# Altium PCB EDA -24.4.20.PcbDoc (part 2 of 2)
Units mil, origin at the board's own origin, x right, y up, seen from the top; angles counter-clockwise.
Board outline 1259.84 x 1062.87 mil, 4 copper layers (Top1, Gnd2, Signal3, Bottom4), stack 30.634 mil thick; 95 components, 111 nets, 499 pads, 259 vias.
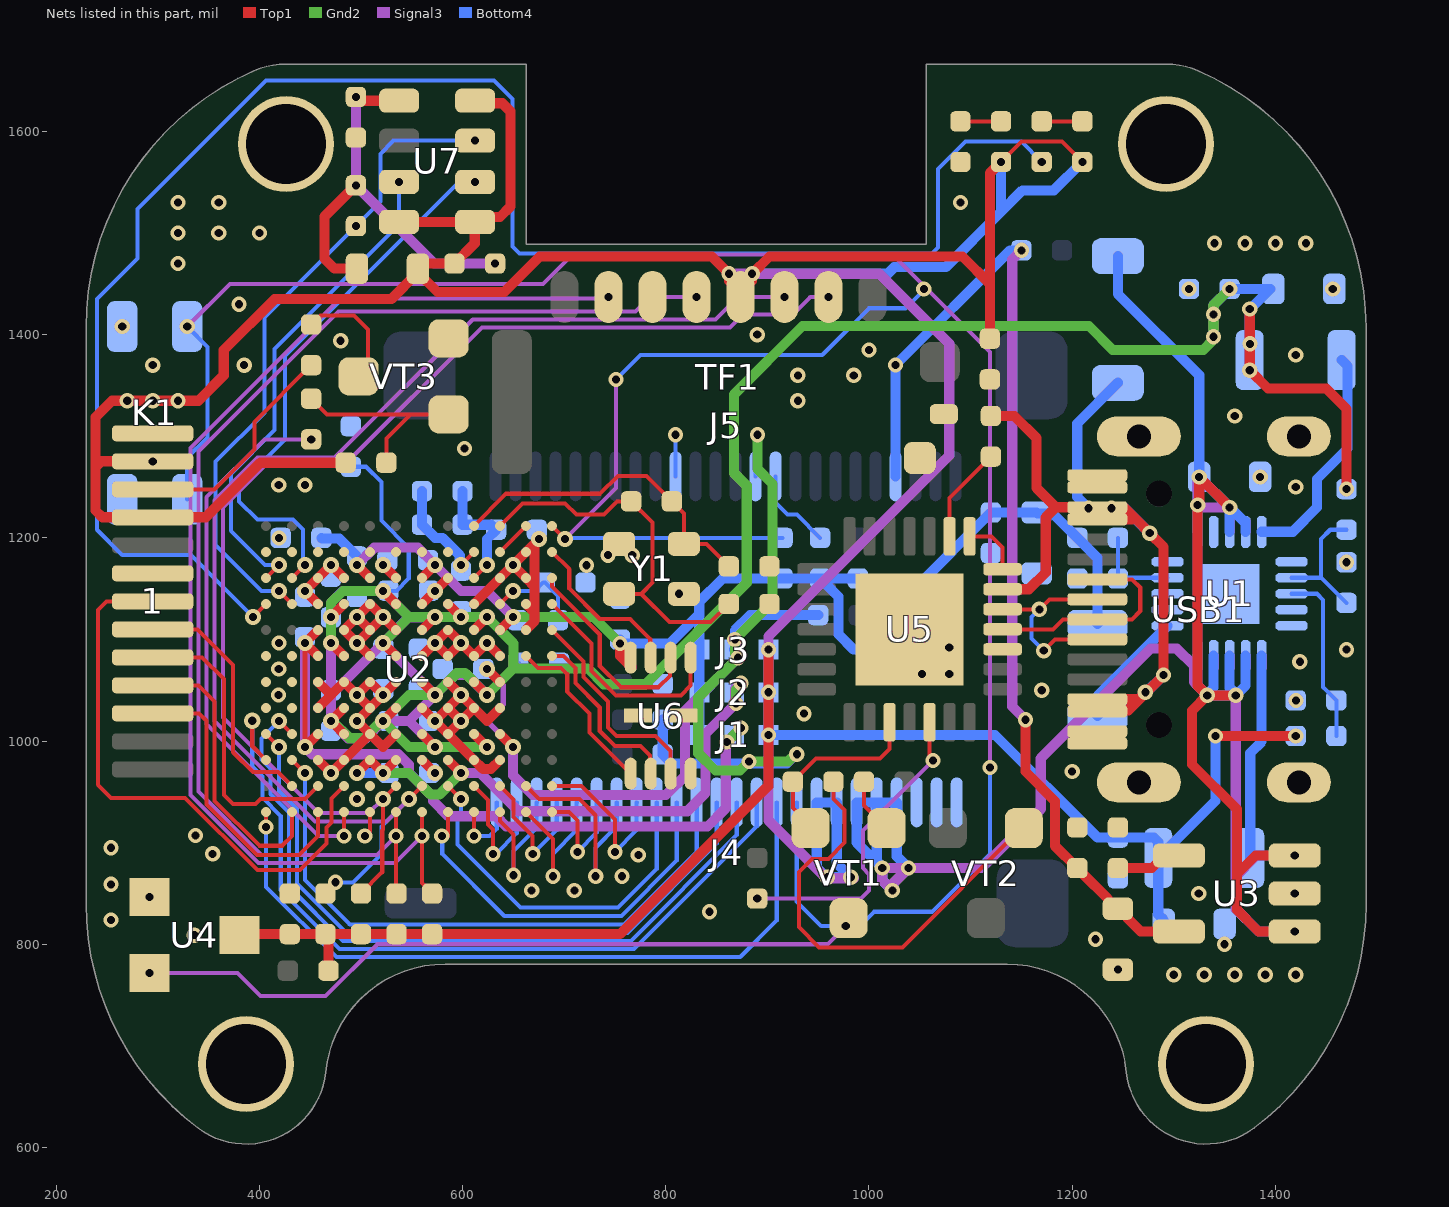
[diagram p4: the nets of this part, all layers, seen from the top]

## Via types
v1: diameter 15, hole 8, Top1 to Bottom4, tented both sides, 192 vias
v2: diameter 16, hole 8, Top1 to Bottom4, tented both sides, 67 vias

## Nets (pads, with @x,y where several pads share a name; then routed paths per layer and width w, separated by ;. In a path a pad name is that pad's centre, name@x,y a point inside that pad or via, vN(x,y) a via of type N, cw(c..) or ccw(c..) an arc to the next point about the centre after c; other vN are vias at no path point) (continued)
GND: 1.8 1.13 C1.1 C2.2 C3.1 C4.1 C5.1 C6.1 C7.1 C8.1 C9.1 C10.1 C11.1 C12.1 C13.1 C14.1 C15.1 C16.2 C17.1 C18.1 C19.2 C20.1 C21.2 C22.2 C23.1 C24.2 C25.2 C26.2 C27.2 C30.2 C33.2 C35.2 C36.2 D1.2 J4.22 J4.23 J4.24 J5.15 K1.1 K1.3 pad. R2.1 R4.1 R9.1 R15.1 R23.2 R30.2 TF1.6 TF1.9 TF1.10 U1.1 U1.4 U1.5 U1.12 U1.13 U1.15 U1.17 U1.21 U2.C3 U2.C4 U2.C6 U2.C9 U2.C10 U2.D5 U2.D7 U2.D8 U2.E3 U2.E4 U2.E5 U2.E6 U2.E8 U2.E10 U2.F5 U2.F7 U2.F8 U2.F9 U2.F10 U2.G3 U2.G4 U2.G5 U2.G6 U2.G8 U2.H2 U2.H5 U2.H7 U2.H8 U2.H9 U2.J2 U2.J4 U2.J6 U2.J8 U2.J10 U2.K2 U2.K3 U2.K5 U2.K7 U2.K9 U2.K10 U2.L2 U3.2 U4.1 U5.3 U5.29 U6.4 U6.GNDA U6.GNDB USB1.1 USB1.2 USB1.3 USB1.4 USB1.A1 USB1.A12 USB1.B1 USB1.B12 VT3.2 Y1.2 Y1.4 | length 1297
  Top1 w9.84: U2.C10@457.64,981.46 v2(470.43,968.66) U2.C9@483.23,981.46 496.02,994.25 U2.D8@508.82,1007.05 ; U2.E10@457.64,1032.64 470.43,1045.43 ; U2.F10@457.64,1058.23 470.43,1045.43 ; U2.J10@457.64,1135 v2(444.84,1147.8) U2.K10@457.64,1160.59 v2(470.43,1173.39) U2.K9@483.23,1160.59 ; U2.G8@508.82,1083.82 v2(496.02,1096.61) ; v2(521.61,1173.39) U2.K7@534.41,1160.59 ; U2.D7@534.41,1007.05 521.61,994.25 U2.D8@508.82,1007.05 ; U2.F7@534.41,1058.23 v2(521.61,1045.43) ; U2.H7@534.41,1109.41 v2(521.61,1122.21) ; U2.C6@560,981.46 v2(572.8,968.66) ; U2.E6@560,1032.64 v2(572.8,1019.84) ; U2.G6@560,1083.82 v2(572.8,1096.61) ; U2.J6@560,1135 v2(572.8,1147.8) U2.K5@585.59,1160.59 ; U2.F5@585.59,1058.23 v2(598.39,1045.43) ; U2.J4@611.18,1135 U2.K3@636.77,1160.59 v2(649.57,1173.39) ; U2.C3@636.77,981.46 628.05,972.74 619.9,972.74 U2.C4@611.18,981.46 U2.D5@585.59,1007.05 ; U2.E3@636.77,1032.64 623.98,1019.84 U2.E4@611.18,1032.64 ; U2.G3@636.77,1083.82 623.98,1096.61 U2.G4@611.18,1083.82 v2(598.39,1096.61) ; U2.H2@662.36,1109.41 662.36,1109.57 671,1118.21 671,1126.36 ; U2.J2@662.36,1134.84 U2.J2@662.36,1135 671,1126.36 ; 470.43,1045.43 U2.F9@483.23,1058.23 v2(496.02,1045.43) ; v2(496.02,1045.43) U2.E8@508.82,1032.64 ; v2(496.02,1045.43) U2.F8@508.82,1058.23 v2(521.61,1045.43) ; v2(496.02,1096.61) U2.H9@483.23,1109.41 v2(496.02,1122.21) ; v2(496.02,1096.61) U2.H8@508.82,1109.41 ; v2(496.02,1122.21) U2.J8@508.82,1135 v2(521.61,1122.21) ; v2(496.02,1122.21) U2.H8@508.82,1109.41 ; U2.D8@508.82,1007.05 v2(496.02,1019.84) U2.E8@508.82,1032.64 ; U2.E8@508.82,1032.64 v2(521.61,1045.43) ; U2.H8@508.82,1109.41 v2(521.61,1122.21) ; v2(572.8,1019.84) U2.E5@585.59,1032.64 ; v2(572.8,1019.84) U2.D5@585.59,1007.05 ; v2(572.8,1096.61) U2.H5@585.59,1109.41 v2(598.39,1096.61) ; v2(572.8,1096.61) U2.G5@585.59,1083.82 v2(598.39,1096.61) ; U2.D5@585.59,1007.05 v2(598.39,1019.84) ; U2.E5@585.59,1032.64 v2(598.39,1045.43) ; U2.E5@585.59,1032.64 v2(598.39,1019.84) ; v2(598.39,1019.84) U2.E4@611.18,1032.64 ; v2(598.39,1045.43) U2.E4@611.18,1032.64 ; v2(649.57,1173.39) U2.L2@662.36,1186.18 v2(675.16,1198.98) 675.16,1197.31 671,1193.15 671,1151.95 ; v2(649.57,1173.39) U2.K2@662.36,1160.59 671,1151.95 ; 671,1126.36 671,1151.95
  Bottom4 w4: J5.15@809.62,1260.59 v1(809.62,1301.51)
  other v1: 1300,770 1330,770 1360,770 1390,770 1420,770 1245,775 1350,800 1223,805 336,809 254,824 843,832 291.71,846.4 1324.57,850 1419.06,850 668,853 710,853 254,859 757,867 773,888 354,889 254,895 337,907 1200,970 936,1027 1420.31,1040 418.75,1045.39 1170,1050 1052,1066 1079,1066 419,1071 1424.06,1078.07 1470,1090 1079,1092 419.25,1096.61 813,1145 722,1173 1470,1176 743,1183 767,1183 419.25,1200 1420,1250 419,1252 445,1252 1385,1260 602,1288 1360,1320 930,1335 930,1360 985,1360 295,1370 385,1370 1420,1380 1000,1385 480,1394 890,1400 265,1408 380,1430 1315,1445 1456.5,1445 320,1470 1340,1490 1370,1490 1400,1490 1430,1490 320,1500 360,1500 400,1500 320,1530 360,1530 1090,1530
  other v2: 496.02,943.07 623.98,1096.61
IO_6: U2.G11
IO_7: U2.G12
IO_8: U2.F11
IO_9: U2.F12
IO_10: U2.E11
IO_11: U2.E12
IO_12: J4.13 U2.D11 | length 737.9
  Top1 w4: v2(419.25,1019.84) U2.D11@432.05,1007.05
  Bottom4 w4: v2(419.25,1019.84) 402,1002.59 402,982 411,973 411,947.69 429,929.69 429,856.63 482.33,803.29 765.55,803.29 869.83,907.57 J4.13@869.83,939.71
IO_13: J4.12 U2.D12 | length 670
  Top1 w4: U2.D12@406.46,1007.05 v2(419.25,994.25)
  Bottom4 w4: v2(419.25,994.25) 419.25,950.75 437,933 437,859.94 485.65,811.29 762.23,811.29 850.14,899.2 J4.12@850.14,939.71
IO_14: J4.11 U2.C11 | length 605.7
  Top1 w4: U2.C11@432.05,981.46 v2(444.84,968.66)
  Bottom4 w4: v2(444.84,968.66) 445,968.5 445,863.25 488.96,819.29 758.92,819.29 830.46,890.83 J4.11@830.46,939.71
IO_15: J4.14 U2.C12 | length 788.7
  Top1 w4: v2(393,1020) 393,994.91 U2.C12@406.46,981.46
  Bottom4 w4: v2(393,1020) 393,975 403,965 403,944.37 421,926.37 421,853.31 479.02,795.29 768.86,795.29 889.51,915.94 J4.14@889.51,939.71
IO_17: J4.15 U2.A12 | length 736.5
  Top1 w4: v1(406.46,915.46) U2.A12@406.46,930.28
  Bottom4 w4: v1(406.46,915.46) 406.46,856.54 475.71,787.29 873.29,787.29 909.2,823.2 J4.15@909.2,939.71
IO_18: 1.6 U2.B11 | length 251.3
  Top1 w4: 1.6@295,1110 339,1110 374,1075 374,989 393.63,969.37 418.55,969.37 U2.B11@432.05,955.87
IO_19: 1.4 U2.A11 | length 287.5
  Top1 w4: 1.4@295,1054.88 340.13,1054.88 356,1039.02 356,941 400,897 422.5,897 432.05,906.54 U2.A11@432.05,930.28
IO_20: 1.5 U2.B10 | length 296.6
  Top1 w4: 1.5@295,1082.44 343.56,1082.44 365,1061 365,947 374,938 396,938 401,943 444.77,943 U2.B10@457.64,955.87
IO_21: 1.3 U2.A10 | length 300
  Top1 w4: 1.3@295,1027.32 340.68,1027.32 348,1020 348,937.69 397.69,888 439.09,888 457.64,906.54 U2.A10@457.64,930.28
IO_22: 1.7 U2.B9 | length 564.1
  Top1 w4: 1.7@295,1137.56 249.56,1137.56 241,1129 241,957 254,944 327,944 398,873 440,873 466,899 466,915 471,920 471,943.64 U2.B9@483.23,955.87
IO_23: R20.2 U2.A9 | length 555.5
  Top1 w4: v1(483.23,906.54) U2.A9@483.23,930.28
  Signal3 w4: v1@452,1297 v1(451,1297) 405,1297 348,1240 348,1016.62 458.08,906.54 v1(483.23,906.54)
IO_24: U2.B8
IO_25: U2.A8 | length 25.8
  Top1 w4: v1(503.82,906.54) 508.82,911.54 U2.A8@508.82,930.28
IO_26: R24.1 TF1.2 U2.B7 | length 1211.4
  Top1 w4: R24.1@500,850 520.91,870.91 520.91,912.14 521.61,912.84 v2(521.61,943.07) U2.B7@534.41,955.87
  Signal3 w4: v2(521.61,943.07) 507.54,929 458.25,929 364,1023.25 364,1230 405,1271 483,1271 619,1407 863.21,1407 876.21,1420 925,1420 942.21,1437.21 v1(960.2,1437.21)
IO_27: R26.1 TF1.5 U2.A7 | length 1196.4
  Top1 w4: U2.A7@534.41,930.28 v1(534.41,906.54) 534.41,850.59 R26.1@535,850
  Signal3 w4: v1(534.41,906.54) 515.87,888 402.31,888 340,950.31 340,1285 478,1423 770,1423 784.21,1437.21 v1(830.28,1437.21)
IO_28: R25.1 TF1.3 U2.B6 | length 1256.9
  Top1 w4: R25.1@465,850 v1@475.5,860.5 ; v2(547.2,943.07) U2.B6@560,955.87
  Signal3 w4: v2(547.2,943.07) 525.13,921 454.94,921 356,1019.94 356,1236.69 398.31,1279 474,1279 610,1415 849,1415 871.21,1437.21 v1(916.9,1437.21)
  Bottom4 w4: v1(475,861) 492,861 520,889 520,915.87 v2(547.2,943.07)
IO_29: R27.1 TF1.7 U2.A6 | length 1165.8
  Top1 w4: U2.A6@560,930.28 v1(560,906.54) 560,860.34 570,850.34 R27.1@570,850
  Signal3 w4: v1(560,906.54) 533.46,880 399,880 332,947 332,1288.31 479.19,1435.5 741.96,1435.5 v1(743.67,1437.21)
IO_30: J4.9 U2.B5 | length 367.7
  Top1 w4: U2.B5@585.59,955.87 v2(598.39,943.07)
  Bottom4 w4: v2(598.39,943.07) 598.39,928.39 595,925 595,898 657,836 753,836 791.09,874.09 J4.9@791.09,939.71
IO_31: J4.10 U2.A5 | length 377.3
  Top1 w4: v1@585.59,906.54 U2.A5@585.59,930.28
  Bottom4 w4: v1(579.59,906.54) 580,906.13 580,889 641,828 756.31,828 810.77,882.46 J4.10@810.77,939.71
IO_32: J4.2 U2.B4 | length 136.8
  Top1 w4: U2.B4@611.18,955.87 625,942.05 625,918 630,913 v1(630,889)
  Bottom4 w4: v1(630,889) 633,889 653.29,909.29 J4.2@653.29,939.71
IO_33: J4.1 U2.A4 | length 75.2
  Top1 w4: v1(611.18,906.54) U2.A4@611.18,930.28
  Bottom4 w4: v1(611.18,906.54) 626.54,906.54 633.61,913.61 J4.1@633.61,939.71
IO_34: J4.4 U2.B3 | length 140.7
  Top1 w4: U2.B3@636.77,955.87 650,942.64 650,925.36 669,906.36 v1(669,889)
  Bottom4 w4: v1(669,889) 692.66,912.66 J4.4@692.66,939.71
IO_35: J4.3 U2.A3 | length 149
  Top1 w4: U2.A3@636.77,930.28 636.77,921.23 650,908 v1(650,868)
  Bottom4 w4: v1(650,868) 650,892 672.57,914.57 672.57,939.3 J4.3@672.98,939.71
IO_36: J4.5 U2.A2 | length 156.7
  Top1 w4: U2.A2@662.36,930.28 689,903.64 v1(689,867)
  Bottom4 w4: v1(689,867) 689,889 712.26,912.26 712.26,939.62 J4.5@712.35,939.71
IO_37: J4.6 U2.A1 | length 116.1
  Top1 w4: U2.A1@687.95,930.28 704.72,930.28 713,922 v1(713,891)
  Bottom4 w4: v1(713,891) 732.03,910.03 J4.6@732.03,939.71
IO_38: J4.7 U2.B2 | length 221.9
  Top1 w4: U2.B2@662.36,955.87 675.23,943 715,943 731,927 v1(731,867)
  Bottom4 w4: v1(731,867) 731,895 751.72,915.72 J4.7@751.72,939.71
IO_39: J4.8 U2.B1 | length 165.2
  Top1 w4: U2.B1@687.95,955.87 717.13,955.87 750,923 v1(750,891)
  Bottom4 w4: v1(750,891) 771.29,912.29 771.29,939.59 J4.8@771.4,939.71
LEDK: 1.11 R18.2 | length 222.4
  Top1 w4: 1.11@295,1247.8 355.8,1247.8 395,1287 395,1314 R18.2@451,1370
MIC_AGND: C31.1 C32.2 R19.2 R23.1 U7.1 | length 421
  Top1 w10: v1(495,1547) 464,1516 464,1475 474,1465 C32.2@496,1465 ; v1(495,1634) 498.69,1630.32 U7.1@537.6,1630.32
  Signal3 w10: v1(495,1634) v1(495,1547) 572,1470 v1(632,1470)
MIC_DATA0: R19.1 U2.J11 U7.7 | length 650.1
  Top1 w4: v2(419.25,1147.8) U2.J11@432.05,1135
  Bottom4 w4: v2(419.25,1147.8) 402,1147.8 357,1192.8 357,1275 405,1323 405,1417 v1(495,1507) 519,1531 519,1578 531.94,1590.94 v1(612.4,1590.94)
MIC_SCLK0: U2.K11 U7.6 | length 548.1
  Top1 w4: U2.K11@432.05,1160.59 v2(444.84,1173.39)
  Bottom4 w4: v2(444.84,1173.39) 442.84,1175.39 442.84,1208.16 433,1218 398,1218 380,1236 380,1252 425,1297 425,1379 596.32,1550.32 v1(612.4,1550.32)
MIC_WS0: U2.K12 U7.3 | length 491.2
  Top1 w4: U2.K12@406.46,1160.59 v2(419.25,1173.39)
  Bottom4 w4: v2(419.25,1173.39) 405.61,1173.39 372,1207 372,1263 415,1306 415,1386 537.6,1508.6 v1(537.6,1550.32)
NetC20_2: C20.2 U3.4 | length 65.2
  Top1 w10: C20.2@1245,875 1278.61,875 1291.01,887.4 U3.4@1305.06,887.4
NetC25_1: C25.1 R8.2 U2.J3 | length 95.3
  Top1 w4: U2.J3@636.77,1135 v2(649.57,1147.8)
  Bottom4 w4: v2(649.57,1147.8) 671.17,1147.8 679.38,1156 C25.1@681,1156 694,1143 R8.2@694,1119
NetC26_1: C26.1 R12.2 U2.M3 Y1.1 | length 377.9
  Top1 w4: U2.M3@636.77,1211.77 659,1234 701,1234 712,1223 739,1223 752,1236 R12.2@766,1236 786.98,1215.02 786.98,1155.98 775.84,1144.84 ; Y1.1@755.92,1144.84 775.84,1144.84 ; C26.1@862,1135 844,1117 803.69,1117 775.84,1144.84
NetC27_1: C27.1 R12.1 U2.M4 Y1.3 | length 325.7
  Top1 w4: U2.M4@611.18,1211.77 642.87,1243.46 735.46,1243.46 753,1261 781,1261 R12.1@806,1236 817.87,1224.13 Y1.3@817.87,1194.06 839.94,1194.06 C27.1@862,1172
NetC28_1: C28.1 C29.1 R15.2 U2.K4 | length 124.5
  Top1 w4: U2.K4@611.18,1160.59 v2(623.98,1173.39)
  Bottom4 w10: C28.1@600,1246 C29.1@600,1213 628,1213 R15.2@633,1208 623.98,1198.98 v2(623.98,1173.39)
NetC28_2: C28.2 C29.2 R14.1 U2.L4 | length 110.7
  Top1 w4: v2(598.39,1173.39) U2.L4@611.18,1186.18
  Bottom4 w10: C28.2@560,1246 C29.2@560,1213 573,1200 580,1200 597.24,1182.76 597.24,1174.53 v2(598.39,1173.39)
NetD1_1: D1.1 R6.2 | length 40
  Top1 w4: D1.1@1090,1610 R6.2@1130,1610
NetD2_1: D2.1 R10.2 | length 40
  Top1 w4: D2.1@1170,1610 R10.2@1210,1610
NetJ5_10: J5.10 R28.1 | length 84.1
  Bottom4 w4: J5.10@908.05,1260.59 908.05,1234.95 920,1223 929,1223 R28.1@952,1200
NetL1_1: L1.1 U1.11 | length 117.4
  Bottom4 w10: L1.1@1225,1024.72 1225,1044.53 U1.11@1293.98,1113.5
NetL2_1: L2.1 U1.6 | length 203.6
  Bottom4 w10: L2.1@1375.28,885 1375.28,988.28 1386.5,999.5 U1.6@1386.5,1083.98
NetL3_1: L3.1 U1.20 | length 224.2
  Bottom4 w10: U1.20@1386.5,1206.02 1417.02,1206.02 1441,1230 1441,1258 1471,1288 1471,1369.28 L3.1@1465.28,1375
NetR1_1: R1.1 R2.2 U1.14 | length 89.3
  Bottom4 w4: R1.1@1245,1200 R2.2@1245,1160 1245.75,1160.75 U1.14@1293.98,1160.75
NetR3_1: R3.1 R4.2 U1.3 | length 172.8
  Bottom4 w4: U1.3@1416.02,1145 1441,1145 1447,1139 1447,1053 R4.2@1460,1040 R3.1@1460,1005
NetR7_1: R7.1 R9.2 U1.2 | length 131.1
  Bottom4 w4: U1.2@1416.02,1160.75 1445,1160.75 ; R9.2@1470,1136 1445,1161 1445,1199 1454,1208 R7.1@1470,1208
NetR13_2: R13.2 U5.9 | length 95.3
  Top1 w4: U5.9@1079.37,1201.5 1079.37,1239.37 R13.2@1120,1280
NetR16_2: R16.2 U5.26 | length 308.4
  Top1 w4: U5.26@1059.69,1018.5 1059.69,984.32 v1@1061,983
  Signal3 w4: v1(890,845) 992,845 1000,853 1000,868.91 994,874.91 994,912 v1(1063,981)
NetR17_2: R17.2 VT1.1 | length 55
  Top1 w4: R17.2@995,960 995,936.69 VT1.1@1017.4,914.29
NetR18_1: R18.1 VT3.3 | length 115.4
  Top1 w4: R18.1@451,1410 460,1419 493,1419 507,1405 507,1368.29 VT3.3@497.71,1359
NetR20_1: R20.1 R21.1 VT3.1 | length 199
  Top1 w4: R20.1@451,1337 466.4,1321.6 548.6,1321.6 ; R21.1@525,1274 525,1298 548.6,1321.6 ; VT3.1@586.29,1321.6 548.6,1321.6
NetR22_2: R22.2 VT2.1 | length 453.8
  Top1 w4: R22.2@965,960 965,943 976,932 976,900 960,884 944,884 931,871 931,817 951,797 1033,797 1150.29,914.29 VT2.1@1152.4,914.29
NetU2_G1: U2.G1 U6.2 | length 177.4
  Top1 w4: U2.G1@687.95,1083.82 699.18,1083.82 711,1072 711,1057 735,1033 735,1010 750,995 775,995 784.28,985.72 784.28,968.79 U6.2@785.16,967.91
NetU2_G2: U2.G2 U6.1 | length 172
  Top1 w4: U2.G2@662.36,1083.82 674.18,1072 697,1072 703,1066 703,1049 725,1027 725,1008.39 U6.1@765.47,967.91
NetU2_H1: U2.H1 U6.3 | length 212.6
  Top1 w4: U2.H1@687.95,1109.41 719,1078.36 719,1063 743,1039 743,1013.31 751.31,1005 790,1005 804.84,990.16 U6.3@804.84,967.91
NetU2_J1: U2.J1 U6.5 | length 221.1
  Top1 w4: U2.J1@687.95,1135 727,1095.95 727,1069 751,1045 815,1045 824.53,1054.53 U6.5@824.53,1082.09
NetU2_K1: U2.K1 U6.6 | length 206.8
  Top1 w4: U2.K1@687.95,1160.59 687.95,1152.05 735,1105 735,1074 756,1053 793,1053 804.12,1064.12 804.12,1081.37 U6.6@804.84,1082.09
NetU2_L1: U2.L1 U6.7 | length 161.9
  Top1 w4: U2.L1@687.95,1186.18 705,1169.13 705,1150 735,1120 765,1120 784.7,1100.3 784.7,1082.55 U6.7@785.16,1082.09
NetU2_L3: U2.L3 U2.M2 | length 36.2
  Top1 w4: U2.L3@636.77,1186.18 U2.M2@662.36,1211.77
NetU5_7: U5.7 U5.8 | length 58.4
  Top1 w4: U5.8@1099.06,1201.5 1120.5,1201.5 1131.5,1190.5 U5.7@1131.5,1169.06
RESETN: J4.16 K1.2 K1.4 R11.1 U2.M1 U4.2 VT1.3 | length 3344
  Top1 w4: U2.M1@687.95,1211.77 v2(700.75,1198.98)
  Signal3 w4: v1(291.71,771.6) 378.4,771.6 401,749 465,749 516,800 959.15,800 v1(977.15,818) ; v1(329,1408) 371,1450 679,1450 708,1479 1023,1479 1119,1383 v1(1119,974) ; v2(700.75,1198.98) 751,1249.23 v1(751,1356)
  Bottom4 w4: K1.4@329,1238 329,1279 349,1299 349,1388 v1(329,1408) ; v2@701.77,1200 R11.1@915,1200 ; v1(751,1356) 775,1380 954,1380 1000,1426 1036,1426 1052,1442 v1@1052,1450 ; J4.16@928.88,939.71 928.88,842.12 953,818 v1(977.15,818) 991,818 1005,832 1062,832 1119,889 v1(1119,974)
  other v1: 1054,1445
RTS: R22.1 U5.24 VT1.2 | length 187.9
  Top1 w4: VT1.2@942.6,914.29 942.6,916.72 925,934.32 R22.1@925,960 948,983 1011,983 1020.32,992.32 U5.24@1020.32,1018.5
SPI0_D0: U2.L12
SPI0_D1: U2.L11
SPI0_D2: U2.L10
SPI0_D3: U2.L9
SPI0_D4: U2.L8
SPI0_D5: U2.L7
SPI0_D6: U2.L6
SPI0_D7: U2.L5
USB-PWR-DM: U5.5 USB1.A7 USB1.B7 | length 203.4
  Top1 w4: U5.5@1131.5,1129.69 v1(1167.69,1129.69) 1177.53,1139.53 USB1.A7@1224.69,1139.53 ; v1(1172,1089) 1183.16,1100.16 USB1.B7@1224.69,1100.16
  Bottom4 w4: v1(1167.69,1129.69) 1160,1122 1160,1101 v1(1172,1089)
USB-PWR-DP: U5.4 USB1.A6 USB1.B6 | length 211.7
  Top1 w4: U5.4@1131.5,1110 1181,1110 1190.84,1119.84 USB1.A6@1224.69,1119.84 1258.84,1119.84 1267,1128 1267,1151 1258.79,1159.21 USB1.B6@1224.69,1159.21
USR_LED: D2.2 U2.J12 | length 1736.1
  Top1 w4: v2(393.66,1122.2) U2.J12@406.46,1135
  Bottom4 w4: v2(393.66,1122.2) 332.86,1183 265,1183 240,1208 240,1435 280,1475 280,1523.6 406.4,1650 631,1650 649,1632 649,1487 656,1480 1062,1480 1068,1486 1068,1563 1095,1590 1150,1590 v1(1170,1570)
VCC_0V9: C4.2 C5.2 C6.2 C7.2 C8.2 C9.2 C10.2 C11.2 C23.2 C24.1 L3.2 R7.2 R14.2 U2.D4 U2.D6 U2.D9 U2.E7 U2.E9 U2.F4 U2.F6 U2.G7 U2.G9 U2.H4 U2.H6 U2.J5 U2.J7 U2.J9 | length 3326.5
  Top1 w10: v2(470.43,1096.61) U2.G9@483.23,1083.82 ; v2(470.43,1122.2) U2.J9@483.23,1135 ; U2.D9@483.23,1007.05 v2(470.43,1019.84) U2.E9@483.23,1032.64 ; v2(521.61,1019.84) U2.E7@534.41,1032.64 ; v2(521.61,1096.61) U2.G7@534.41,1083.82 ; v2(521.61,1147.8) U2.J7@534.41,1135 ; U2.D6@560,1007.05 v2(572.8,994.25) ; U2.F6@560,1058.23 v2(572.8,1045.43) ; U2.H6@560,1109.41 v2(572.8,1122.21) ; U2.J5@585.59,1135 v2(598.39,1122.21) ; U2.D4@611.18,1007.05 v2(623.98,994.25) ; U2.F4@611.18,1058.23 v2(623.98,1045.43) ; U2.H4@611.18,1109.41 v2(623.98,1122.21) ; v1(1374.72,1425.28) v1(1374.72,1365) 1392.72,1347 1450,1347 1470,1327 v1(1470,1248)
  Signal3 w10: v2(623.98,994.25) v2(572.8,994.25) 547.21,1019.84 ; v2(623.98,1045.43) 604.41,1065 592.36,1065 v2(572.8,1045.43) ; v2(623.98,1122.21) v2(572.8,1122.21) 572.33,1121.74 546.74,1121.74 ; 470.43,1045.43 v2(470.43,1096.61) v2(470.43,1122.2) 470.43,1136.43 481.8,1147.8 v2(521.61,1147.8) 546.74,1122.67 546.74,1121.74 ; 470.43,1045.43 v2(521.61,1096.61) ; 470.43,1045.43 v2(470.43,1019.84) 487.43,1002.84 504.61,1002.84 v2(521.61,1019.84) 547.21,1019.84 ; v2(521.61,1096.61) 546.74,1121.74 ; v2(521.61,1096.61) v2(572.8,1045.43) ; 547.21,1019.84 v2(572.8,1045.43)
  Gnd2 w10: v2(470.43,1019.84) 471.84,1019.84 488.84,1002.84 503.06,1002.84 520.06,1019.84 v2(521.61,1019.84) ; v2(470.43,1096.61) v2(470.43,1122.2) 470.43,1136 482.23,1147.8 v2(521.61,1147.8) 547.2,1122.21 ; v2(521.61,1096.61) 547.2,1122.21 ; v2(623.98,994.25) v2(572.8,994.25) 547.2,994.25 v2(521.61,1019.84) ; v1(1355,1445) 1339,1429 v1(1339,1420) v1(1339,1398) 1339,1395 1329,1385 1240,1385 1216.5,1408.5 934.5,1408.5 867,1341 867,1264 879.75,1251.25 879.75,1155.75 780,1056 739,1056 723.54,1071.46 650,1071.46 ; v2(521.61,1019.84) 547.2,1045.43 v2(572.8,1045.43) 594.24,1066.88 602.53,1066.88 v2(623.98,1045.43) 650,1071.46 ; 547.2,1122.21 v2(572.8,1122.21) v2(623.98,1122.21) 650,1096.18 650,1071.46
  Bottom4 w4: C5.2@490,1270 504.82,1270 520,1254.82 520,1217 547,1190 547,1160 534.8,1147.8 527.2,1147.8 C11.2@527,1148 ; v2(623.98,1045.43) C10.2@655.27,1076.73
  Bottom4 w10: v1(1339,1398) v1(1339,1420) 1339,1429 v1(1355,1445) 1395,1445 1375.28,1425.28 v1(1374.72,1425.28) L3.2@1374.72,1375
  other v1: 1375,1391
VCC_1V8: C1.2 C2.1 C12.2 C13.2 C14.2 C30.1 C37.2 J1.3 J2.3 J3.3 L1.2 R1.2 R8.1 R11.2 R28.2 U2.H3 U2.K6 U2.K8 U6.8 | length 1307
  Top1 w10: v2(496.02,1173.39) U2.K8@508.82,1160.59 ; U2.K6@560,1160.59 v2(572.8,1173.39) ; U2.H3@636.77,1109.41 v2(649.57,1122.21) ; v1(755,1096) 755,1084 U6.8@766,1073
  Signal3 w10: v2(496.02,1173.39) 513.02,1190.39 555.8,1190.39 v2(572.8,1173.39) 598.39,1147.8 623.98,1147.8 v2(649.57,1122.21)
  Gnd2 w10: v2(649.57,1122.21) 728.79,1122.21 v1(755,1096)
  Bottom4 w10: C12.2@461,1200 461.73,1199.27 478.55,1199.27 C14.2@496.02,1181.8 ; C30.1@755,1100 759,1096 804,1096 833,1125 ; J1.3@833,1006 J2.3@833,1048 J3.3@833,1090 833,1125 ; C37.2@989,1160 R28.2@952,1160 ; L1.2@1225,1115.28 1225,1180 R1.2@1205,1200 1181,1224 1166,1224 C1.2@1165,1225 C2.1@1120,1225 1045,1150 1045,1105 1030,1090 985,1090 970,1105 970,1142 R28.2@952,1160 ; 833,1125 833,1137 856,1160 R11.2@915,1160 R28.2@952,1160
VCC_2V5: C17.2 C18.2 C34.2 J5.4 U3.5 | length 1048.7
  Top1 w10: v1(1154,1021) 1154,970 1183,941 1183,897 C17.2@1205,875 1210,870 1235.31,844.69 1235.31,840.96 1241.27,835 C18.2@1245,835 1248.73,835 1254.69,829.04 1254.69,825.31 1267.4,812.6 U3.5@1305.06,812.6
  Signal3 w10: v1(1150,1483) 1141,1474 1141,1034 v1(1154,1021)
  Bottom4 w10: J5.4@1026.16,1260.59 v1(1026.16,1370.16) 1139,1483 v1(1150,1483)
VCC_3V3: 1.10 1.12 C15.2 C16.1 C31.2 C32.1 C33.1 C36.1 J1.1 J2.1 J3.1 J4.17 J4.18 L2.2 R3.2 R5.2 R6.1 R10.1 R21.2 R24.2 R25.2 R26.2 R27.2 TF1.4 U4.3 U7.4 U7.5 U7.8 | length 5110.8
  Top1 w4: v1(1130,1570) 1150,1590 1190,1590 v1(1210,1570)
  Top1 w10: v1(295,1275.35) 244.52,1275.35 238.67,1269.5 ; U4.3@380.29,809 381.29,810 C33.1@430,810 R25.2@465,810 R24.2@500,810 R26.2@535,810 R27.2@570,810 755,810 901,956 v1(901,1006) v1(901,1048) v1(901,1090) ; R5.2@468,774 R25.2@468,807 ; R21.2@485,1274 401,1274 347.24,1220.24 1.10@295,1220.24 245.43,1220.24 238.67,1227 238.67,1269.5 ; U7.4@537.6,1510.94 U7.5@612.4,1510.94 ; U7.8@612.4,1630.32 614.88,1627.83 639.17,1627.83 647,1620 647,1526 636.8,1515.8 617.25,1515.8 U7.5@612.4,1510.94 ; TF1.4@862.21,1453 v1(862.21,1460) 845.21,1477 676,1477 641,1442 575.27,1442 C32.1@556,1461.27 ; TF1.4@885,1453 v1(885,1460) 902,1477 1092,1477 1119,1450 ; C36.1@1119,1396 1119,1450 ; v1(1130,1570) 1119,1559 1119,1450 ; v1(1341,1005) v1(1420,1005) ; 238.67,1269.5 238.67,1318.67 255,1335 v1(270,1335) v1(295,1335) v1(320,1335) 340,1335 365,1360 365,1385 415,1435 529.73,1435 C32.1@556,1461.27 ; C32.1@556,1461.27 C32.1@556,1465 561,1470 C31.2@592,1470 611.99,1489.99 611.99,1510.54 U7.5@612.4,1510.94
  Signal3 w10: v1(862.21,1460) v1(885,1460) 1010,1460 1079,1391 1079,1281 901,1103 v1(901,1090) v1(901,1048) v1(901,1006) 901,922 958,865 v1@985,865
  Bottom4 w10: v1(885,1460) 1018.44,1460 1024.94,1466.5 1075.5,1466.5 1130,1521 ; v1(901,1090) v1(901,1048) v1(901,1006) 1124,1006 1225,905 C16.1@1245,905 1280.47,905 1284.72,900.75 L2.2@1284.72,885 ; v1(1130,1570) 1130,1521 ; v1(1210,1570) 1182,1542 1151,1542 1130,1521 ; C15.2@1290,820 1290,824 1284.72,829.28 L2.2@1284.72,885 ; v1(1341,1005) 1341,941.28 L2.2@1284.72,885 ; 948.57,875.43 958,866 v1(959,866) v1(982,866) 968.25,879.75 J4.18@968.25,939.71 J4.17@948.57,939.71 948.57,875.43
VCC_BANK_012: C19.1 J1.2 U2.D10 U2.G10 U2.H10 | length 823
  Top1 w5: v2(444.84,994.25) v2(444.84,1096.61)
  Top1 w9.84: U2.G10@457.64,1083.82 v2(444.84,1096.61) U2.H10@457.64,1109.41
  Top1 w10: v2(444.84,994.25) U2.D10@457.64,1007.05
  Signal3 w10: v2(444.84,1096.61) v2(444.84,994.25) 452.09,987 537,987 547,977 547,969 571,945 571,941 586,926 633,926 643,916 841,916 859,934 v1@859,996 ; v1(860,999) v1(874,1013)
  Gnd2 w10: v1(860,999) v1(874,1013) ; v1@873.04,1011.04 v1@874,1012
VCC_BANK_67: C22.1 C38.2 J3.2 J5.11 R29.2 R31.2 U2.D3 U2.F3 | length 1291.9
  Top1 w10: v2(623.98,1071.02) U2.F3@636.77,1058.23 ; U2.D3@636.77,1007.05 v2(649.57,994.25)
  Signal3 w5: v2(623.98,1071.02) 640,1055 640,1036 625.98,1021.98 625.98,1017.84 v2(649.57,994.25)
  Signal3 w10: v2(649.57,994.25) 649.57,966.43 669,947 800,947 819,966 819,1030 v1(871,1082) 870.81,1082.19 870.81,1095.81 867.98,1098.63 v1(867.98,1099.98)
  Gnd2 w10: v1(890.36,1301.51) 890.36,1267.64 905,1253 905,1137 v1(867.98,1099.98) 868.18,1099.79 868.18,1086.18 871,1083.35 v1(871,1082) 832,1043 832,988 849,971 873,971 v1(882,980) 920.65,980 927.65,987 v1(929,987)
  Bottom4 w4: J5.11@888.36,1260.59 v1@888.36,1301.51
  Bottom4 w10: R29.2@797,1021 R31.2@797,987 806,978 919,978 v1@930,989 ; J3.2@867,1090 867.98,1090.98 v1(867.98,1099.98) 867.98,1108.98 883,1124 C38.2@950,1124
VCC_BANK_345: C21.1 J2.2 U2.C5 U2.C7 U2.C8 | length 601.6
  Top1 w10: v2(496.02,968.66) U2.C8@508.82,981.46 v2(521.61,968.66) U2.C7@534.41,981.46 ; U2.C5@585.59,981.46 v2(598.39,968.66)
  Signal3 w10: v2(598.39,968.66) 617.34,968.66 655,931 821.2,931 839,948.8 839,1007 v1(869,1037) 868.04,1037.96 868.04,1041.49 868,1041.54 868,1051 v1(874,1057)
  Gnd2 w10: v2(521.61,968.66) 547.34,968.66 568.72,947.28 577.01,947.28 v2(598.39,968.66) ; v1(869,1037) 869.18,1037.18 869.18,1050.82 874,1055.65 v1(874,1057)
  Bottom4 w10: v2(496.02,968.66) v2(521.61,968.66)
VIN: C3.2 D3.2 J4.19 J4.20 J4.21 U1.7 U1.8 U1.9 U1.10 U1.16 U1.18 U1.19 U3.1 U3.3 | length 2741.9
  Top1 w10: v1(1355,1230) v1(1325,1260) 1325,1235.11 1323.5,1233.62 v1(1323.5,1232.26) 1323.5,1054.5 v1(1333,1045) ; v1(1361,1045) v1(1333,1045) ; v1(1419.06,812.6) 1383.4,812.6 1362.14,833.86 1362.14,869.14 ; v1(1419.06,887.4) 1380.4,887.4 1362.14,869.14 ; v1(1333,1045) 1318,1030 1318,977 1362.14,932.86 1362.14,869.14
  Signal3 w10: v1(1419.06,812.6) 1383.4,812.6 1361,835 1361,867 ; v1(1419.06,887.4) 1381.4,887.4 1361,867 ; v1(1039,875) 1023.96,859.96 1023.96,853.96 v1(1023,853) 1013,863 v1(1013,875) v1(1039,875) ; v1(1039,875) 1111,875 1169,933 1169,983 1277,1091 1303,1091 1320,1074 ; 1320,1074 1323.5,1077.5 v1(1323.5,1232.26) ; 1320,1074 1320,1058 v1(1333,1045) v1(1361,1045) 1361,867 ; v1(1323.5,1232.26) 1324.86,1232.26 1327.12,1230 v1(1355,1230) v1(1325,1260) 1325,1258.65 1323.5,1257.15 v1(1323.5,1232.26)
  Bottom4 w10: D3.2@1245,1477.34 1245,1440 1325,1360 v1(1325,1260) ; U1.10@1323.5,1083.98 1323.5,1054.5 v1(1333,1045) ; U1.16@1323.5,1206.02 v1(1323.5,1232.26) 1323.5,1258.5 v1(1325,1260) ; U1.9@1339.25,1083.98 1339.25,1052.61 1333,1046.35 v1(1333,1045) ; U1.8@1355,1083.98 1355,1052.35 1361,1046.35 v1(1361,1045) ; U1.18@1355,1206.02 v1(1355,1230) ; U1.19@1368.23,1216.77 v1(1355,1230) ; U1.7@1370.75,1083.98 1370.75,1054.75 v1(1361,1045) ; U1.19@1370.75,1206.02 U1.19@1370.75,1216.5 ; J4.20@1007.62,939.71 1007.62,881.73 1013,876.35 v1(1013,875) ; J4.20@1007.62,939.71 J4.21@1027.31,939.71 1027.31,886.69 v1(1039,875) ; J4.20@1007.62,939.71 J4.19@987.94,939.71 987.94,900.06 v1(1013,875) ; v1(1013,875) 1013,863 v1(1023,853) 1023.96,853.96 1023.96,859.96 v1(1039,875) ; v1(1013,875) v1(1039,875) ; v1(1325,1260) v1(1355,1230) ; v1(1333,1045) v1(1361,1045)
VUSB: D3.1 R13.1 U5.6 USB1.A4 USB1.A9 USB1.B4 USB1.B9 | length 895.4
  Top1 w10: R13.1@1120,1320 1143,1320 1165,1298 1165,1249 1183.92,1230.08 ; U5.6@1131.5,1149.37 1157.37,1149.37 1174,1166 1174,1220.16 1183.92,1230.08 ; USB1.A4@1224.69,1029.29 1225.6,1030.2 1255.2,1030.2 1266.1,1041.1 ; USB1.B9@1224.69,1041.1 1266.1,1041.1 ; USB1.B4@1224.69,1218.27 1262.73,1218.27 ; 1183.92,1230.08 USB1.A9@1224.69,1230.08 1225.6,1229.17 v1(1238.71,1229.17) 1251.83,1229.17 1262.73,1218.27 ; 1262.73,1218.27 v1(1276.37,1204.63) 1290,1191 v1(1290,1065) 1266.1,1041.1
  Bottom4 w10: D3.1@1245,1352.66 1205,1312.66 1205,1240.17 v1(1216,1229.17) v1(1238.71,1229.17) 1251.83,1229.17 v1(1276.37,1204.63) ; v1(1272,1048) 1273,1048 v1(1290,1065)
pads on no net: 1.1 1.2 1.9 J4. J5. J5.1 J5.23 J5.24 TF1. TF1.1 TF1.8 U5.1 U5.2 U5.10 U5.11 U5.12 U5.13 U5.14 U5.15 U5.16 U5.17 U5.18 U5.19 U5.20 U5.21 U5.22 U5.23 U5.27 U7.2 USB1.0 USB1.A5 USB1.A8 USB1.B5 USB1.B8

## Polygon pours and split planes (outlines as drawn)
GND on Top1 "Top1-No Net" (solid, remove dead copper, pour order 2): 100,1800 1600,1800 1600,500 100,500
GND on Gnd2 "Top1-No Net" (solid, remove dead copper, pour order 4): 100,1800 1600,1800 1600,500 100,500
GND on Signal3 "Top1-No Net" (solid, remove dead copper, pour order 6): 100,1800 1600,1800 1600,500 100,500
GND on Bottom4 "Top1-No Net" (solid, remove dead copper, pour order 8): 100,1800 1600,1800 1600,500 100,500

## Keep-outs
Keep-Out Layer:
  the board outline again, w0.5

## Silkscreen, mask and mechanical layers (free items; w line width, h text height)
Top Overlay:
  text "MIC" at 350,1466.57 h80
  text "A-Eye" at 1302,1396.5 h70
  text "LCD" at 238,1376 h80
  text "K210" at 608,835 h60
  text "Inside" at 608,800 h50
Bottom Overlay:
  lines w5: 847,1121 847,1202
  text "CAMERA" at 639,1466 h80
  text "RESET" at 428,1418 h80 r90
  text "1V8" at 840,1201 h60 r90
  text "3V3" at 888,1200 h60 r90
  text "IO" at 506.32,909.04 h80 r90
Top Solder:
  drawing of 514 lines, arcs and shapes, not listed
  text "Pwr" at 1080.16,1634 h35
  text "Usr" at 1164.8,1634 h35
